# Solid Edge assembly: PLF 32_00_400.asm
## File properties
Title: Zylinder
Author: bmolnar
Template: iso metric assembly.asm
Last saved by: bmolnar
Revision: 11
Application: Solid Edge
Username: bmolnar
Dokumentum tartalom típus: 1
Document Number: PLF 32/00-400
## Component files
Zylinder.par
Platte.par
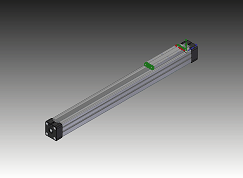
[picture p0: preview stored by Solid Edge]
